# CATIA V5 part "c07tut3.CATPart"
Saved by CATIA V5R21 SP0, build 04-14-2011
Part number: Part1
Bounding box of the stored display mesh (mm): x 0 to 108, y -52.5 to 52.5, z -52.5 to 52.5
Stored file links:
  D:\CATIA V5R21 E-RESOURCES\CATIA-V5R21\catia-v5r21-prt\c07-catia-v5r20-prt\c07-catia-v5r21-tut-3.CATPart
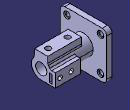
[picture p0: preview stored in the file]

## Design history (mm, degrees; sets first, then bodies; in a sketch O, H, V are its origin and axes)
Body1 (main body)
  Sketch1 on yz-plane, origin (0, 0, 0), H (0, 1, 0), V (0, 0, 1)
    line L1 (52.5, 42.5) -> (52.5, -42.5)
    line L2 (42.5, -52.5) -> (-42.5, -52.5)
    line L3 (-52.5, -42.5) -> (-52.5, 42.5)
    line L4 (-42.5, 52.5) -> (42.5, 52.5)
    point P1 (52.5, 52.5)
    point P2 (52.5, -52.5)
    point P3 (-52.5, -52.5)
    arc A1 centre (42.5, 42.5) radius 10 from (52.5, 42.5) to (42.5, 52.5) ccw
    arc A2 centre (42.5, -42.5) radius 10 from (52.5, -42.5) to (42.5, -52.5) cw
    arc A3 centre (-42.5, -42.5) radius 10 from (-42.5, -52.5) to (-52.5, -42.5) cw
    arc A4 centre (-42.5, 42.5) radius 10 from (-52.5, 42.5) to (-42.5, 52.5) cw
    distance P1 P2 = 105
    radius A1 = 10
    distance P2 P3 = 105
    radius A2 = 10
    radius A3 = 10
    radius A4 = 10
    vertical: L1 V, L3 V
    horizontal: L2 H, L4 H
    equidistance: L1 L3 O, L2 L4 O
    coincidence: L1 P1, L4 P1, L1 P2, L2 P2, L2 P3, L3 P3
    tangency: A1 L1, A1 L4, A2 L1, A2 L2, A3 L2, A3 L3, A4 L3, A4 L4
  Pad1: profile Sketch1, direction (1, 0, 0), length 12
  Sketch2 on face of Pad1, origin (12, 0, 0), H (0, 1, 0), V (0, 0, 1)
    circle A1 centre (0, 0) radius 22
    radius A1 = 22
  Pad2: profile Sketch2, direction (1, 0, 0), length 96
  Sketch3 on face of Pad2, origin (108, 0, 0), H (0, 1, 0), V (0, 0, 1)
    point P1 (-15, 16.0935)
    line L1 (-15, 16.0935) -> (-15, 32)
    line L2 (-15, 32) -> (15, 32)
    line L3 (15, 32) -> (15, 16.0935)
    point P4 (15, 16.0935)
    axis line L4 (0, 0) -> (0, 32)
    point P5 (0, 32)
    reference projected circle E1 centre (0, 0) radius 22 from edge [face of Pad2 | face of Pad2]
    reference projected circle E2 centre (0, 0) radius 22 from edge [face of Pad2 | face of Pad2]
    projected circle E3 centre (0, 0) radius 22 from edge [face of Pad2 | face of Pad2]
    projected arc E4 centre (0, 0) radius 22 from (15, 16.0935) to (-15, 16.0935) ccw from edge [face of Pad2 | face of Pad2]
    length L2 = 30
    distance H L2 = 32
    vertical: L1 V, L3 V, L4 V
    horizontal: L2 H
    midpoint: P5 L2
    coincidence: P4 E1, P1 E2
  Pad3: profile Sketch3, direction (-1, 0, 0), length 76
  Sketch4 on face of Pad2, origin (108, 0, 0), H (0, 1, 0), V (0, 0, 1)
    point P1 (0, -22)
    line L1 (0, -22) -> (32, -22)
    line L2 (32, -22) -> (32, 8)
    line L3 (32, 8) -> (20.4939, 8)
    point P4 (20.4939, 8)
    reference projected circle E1 centre (0, 0) radius 22 from edge of Pad2
    reference projected circle E2 centre (0, 0) radius 22 from edge [face of Pad2 | face of Pad2]
    reference projected circle E3 centre (0, 0) radius 22 from edge [face of Pad2 | face of Pad2]
    projected arc E4 centre (0, 0) radius 22 from (-15, 16.0935) to (15, 16.0935) ccw from edge of Pad3
    projected arc E5 centre (0, 0) radius 22 from (0, -22) to (20.4939, 8) ccw from edge of Pad3
    length L2 = 30
    distance V L2 = 32
    coincidence: P1 V, P4 E1, P1 E2
    horizontal: L1 H, L3 H
    vertical: L2 V
    tangency: L1 E3
  Pad4: profile Sketch4, direction (-1, 0, 0), length 57
  Sketch5 on face of Pad2, origin (108, 0, 0), H (0, 1, 0), V (0, 0, 1)
    line L1 (18.5, 1.5) -> (24.5, 1.5)
    line L2 (24.5, 1.5) -> (24.5, -17.5)
    line L3 (24.5, -17.5) -> (18.5, -17.5)
    line L4 (18.5, -17.5) -> (18.5, 1.5)
    reference projected line E1 (52.5, -42.5) -> (52.5, 42.5) from edge [face of Pad1 | face of Pad1]
    reference projected line E2 (-42.5, -52.5) -> (42.5, -52.5) from edge [face of Pad1 | face of Pad1]
    length L3 = 6
    length L2 = 19
    distance L4 E1 = 34
    distance L3 E2 = 35
    horizontal: L1 H, L3 H
    vertical: L2 V, L4 V
  Pocket1: profile Sketch5, direction (-1, 0, 0), length 50
  Sketch6 on face of Pad2, origin (108, 0, 0), H (0, 1, 0), V (0, 0, 1)
    point P1 (0, 0)
    coincidence: P1 O
  Hole1: placed by Sketch6, at (108, 0, 0) direction (-1, 0, 0), diameter 25, depth 82, V-bottom angle 120
  Sketch7 on face of Pad3, origin (90.7325, -5.9449, 32), H (1, 0, 0), V (0, 1, 0)
    point P1 (1.2675, 5.9449)
    reference projected line E1 (17.2675, -9.0551) -> (-58.7325, -9.0551) from edge [face of Pad3 | face of Pad3]
    reference projected line E2 (17.2675, 20.9449) -> (17.2675, -9.0551) from edge [face of Pad3 | face of Pad3]
    distance P1 E1 = 15
    distance P1 E2 = 16
  Hole2: placed by Sketch7, at (92, 0, 32) direction (0, 0, -1), diameter 12, depth 33.0037, threaded, thread diameter 13.2, thread depth 10, pitch 1
  RectPattern1: of Hole2, direction 1 instances 2, spacing 44, along edge [face of Pad3 | face of Pad3]
  Sketch8 on face of Pad4, origin (86.2721, 32, -2.7131), H (1, 0, 0), V (0, 0, -1)
    point P1 (10.7279, 4.2869)
    reference projected line E1 (21.7279, 19.2869) -> (-35.2721, 19.2869) from edge [face of Pad4 | face of Pad4]
    reference projected line E2 (21.7279, 19.2869) -> (21.7279, -10.7131) from edge [face of Pad4 | face of Pad4]
    distance P1 E1 = 15
    distance E2 P1 = 11
  Hole3: placed by Sketch8, at (97, 32, -7) direction (0, -1, 0), diameter 10, through (limit type 6), threaded, thread diameter 11, thread depth 7.5, pitch 1
  RectPattern2: of Hole3, direction 1 instances 2, spacing 25, along edge [face of Pad4 | face of Pad4], direction 2 instances 2, spacing 76
  Sketch9 on face of Pad1, origin (12, -36.1764, 22.8739), H (0, 1, 0), V (0, 0, 1)
    point P1 (-1.3236, -60.3739)
    reference projected line E1 (-16.3236, 19.6261) -> (-16.3236, -65.3739) from edge [face of Pad1 | face of Pad1]
    reference projected line E2 (-6.3236, -75.3739) -> (78.6764, -75.3739) from edge [face of Pad1 | face of Pad1]
    distance P1 E1 = 15
    distance E2 P1 = 15
  Hole4: placed by Sketch9, at (12, -37.5, -37.5) direction (-1, 0, 0), diameter 10, through (limit type 3), counterbore diameter 15, counterbore depth 3
  RectPattern3: of Hole4, direction 1 instances 2, spacing 76, along edge [face of Pad1 | face of Pad1], direction 2 instances 2, spacing 76, along edge [face of Pad1 | face of Pad1] reversed
  Fillet1: radius 15, on edge [face of Pad3 | face of Pad2]
  Fillet2: radius 5, on edge [face of Pad2 | face of Pad3]; edge [face of Pad2 | face of Pad4]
